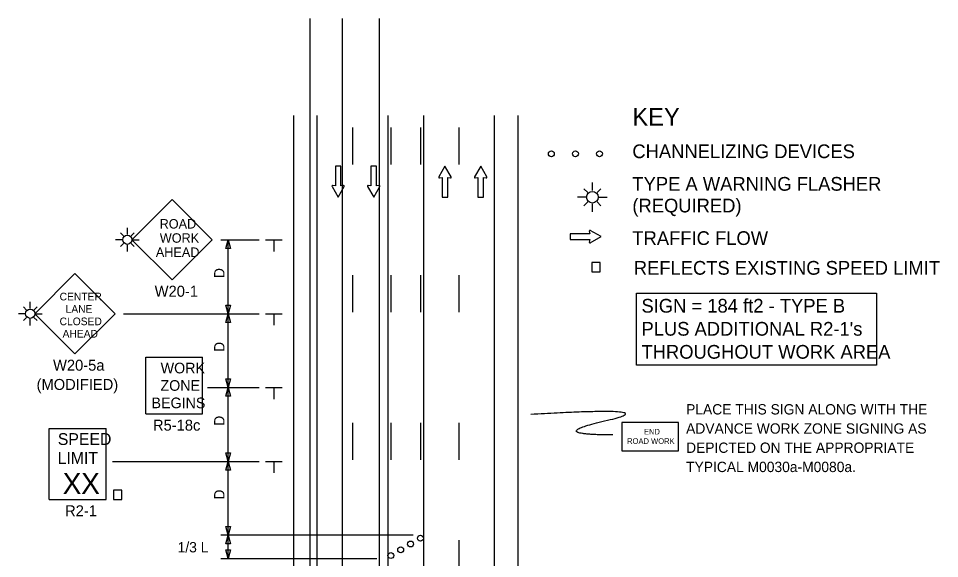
# Model space of a CAD drawing. Extents: x 16765 to 18475, y 6981 to 8262.
# Drawn here: x 16791 to 17415, y 7896 to 8262 of the extents above; entities that cross this region are included whole.
import ezdxf

# ---------------------------------------------------------------- set-up
doc = ezdxf.new("R2010")
doc.units = 0
for name, color, linetype in [('ALI_LEGAL_EX', 7, 'Continuous'), ('MT_SCRATCH_LEVEL_E', 7, 'Continuous'), ('PAVT_EDGE_EX', 7, 'Continuous'), ('TRAFFIC_SIGNS_PR', 7, 'Continuous'), ('TYPICAL_TEXT_DIMEN_EX', 7, 'Continuous'), ('TYPICAL_TEXT_DIMEN_PR', 7, 'Continuous')]:
    doc.layers.add(name, color=color, linetype=linetype)

msp = doc.modelspace()

# ---------------------------------------------------------------- linework, layer by layer
at = {"layer": 'ALI_LEGAL_EX'}
for points in [[(17017.08, 8188.47), (17017.08, 8163.47)], [(17043.08, 8188.47), (17043.08, 8163.47)], [(17063.08, 8188.47), (17063.08, 8163.47)], [(17089.08, 8188.47), (17089.08, 8163.47)], [(17017.08, 8088.47), (17017.08, 8063.47)], [(17043.08, 8088.47), (17043.08, 8063.47)], [(17063.08, 8088.47), (17063.08, 8063.47)], [(17089.08, 8088.47), (17089.08, 8063.47)], [(17017.08, 7988.47), (17017.08, 7963.47)], [(17043.08, 7988.47), (17043.08, 7963.47)], [(17063.08, 7988.47), (17063.08, 7963.47)], [(17089.08, 7988.47), (17089.08, 7963.47)]]:
    msp.add_lwpolyline(points, dxfattribs=at)
at = {"layer": 'MT_SCRATCH_LEVEL_E'}
for p, q in [((17009.24, 8162.18), (17005.5, 8162.18)), ((17005.5, 8162.18), (17005.5, 8148.92)), ((17009.24, 8162.18), (17005.5, 8162.18)), ((17005.5, 8162.18), (17005.5, 8148.92)), ((17009.24, 8148.92), (17009.24, 8162.18)), ((17009.24, 8148.92), (17009.24, 8162.18)), ((17033.31, 8162.18), (17029.57, 8162.18)), ((17029.57, 8162.18), (17029.57, 8148.92)), ((17033.31, 8162.18), (17029.57, 8162.18)), ((17029.57, 8162.18), (17029.57, 8148.92)), ((17033.31, 8148.92), (17033.31, 8162.18)), ((17033.31, 8148.92), (17033.31, 8162.18)), ((17079.72, 8162.18), (17075.61, 8154.94)), ((17079.72, 8162.18), (17075.61, 8154.94)), ((17083.86, 8154.94), (17079.72, 8162.18)), ((17083.86, 8154.94), (17079.72, 8162.18)), ((17103.89, 8162.18), (17099.78, 8154.94)), ((17103.89, 8162.18), (17099.78, 8154.94)), ((17108.03, 8154.94), (17103.89, 8162.18)), ((17108.03, 8154.94), (17103.89, 8162.18)), ((17076.09, 8154.26), (17077.87, 8154.57)), ((17076.09, 8154.26), (17077.87, 8154.57)), ((17077.87, 8154.57), (17077.87, 8141.31)), ((17077.87, 8154.57), (17077.87, 8141.31)), ((17081.61, 8141.31), (17081.61, 8154.57)), ((17081.61, 8154.57), (17083.39, 8154.26)), ((17081.61, 8141.31), (17081.61, 8154.57)), ((17081.61, 8154.57), (17083.39, 8154.26)), ((17100.26, 8154.26), (17102.04, 8154.57)), ((17100.26, 8154.26), (17102.04, 8154.57)), ((17102.04, 8154.57), (17102.04, 8141.31)), ((17102.04, 8154.57), (17102.04, 8141.31)), ((17105.78, 8141.31), (17105.78, 8154.57)), ((17105.78, 8154.57), (17107.56, 8154.26)), ((17105.78, 8141.31), (17105.78, 8154.57)), ((17105.78, 8154.57), (17107.56, 8154.26)), ((17003.24, 8148.55), (17007.39, 8141.31)), ((17003.24, 8148.55), (17007.39, 8141.31)), ((17005.5, 8148.92), (17003.72, 8149.24)), ((17005.5, 8148.92), (17003.72, 8149.24)), ((17007.39, 8141.31), (17011.5, 8148.55)), ((17007.39, 8141.31), (17011.5, 8148.55)), ((17011.02, 8149.24), (17009.24, 8148.92)), ((17011.02, 8149.24), (17009.24, 8148.92)), ((17027.31, 8148.55), (17031.46, 8141.31)), ((17027.31, 8148.55), (17031.46, 8141.31)), ((17029.57, 8148.92), (17027.79, 8149.24)), ((17029.57, 8148.92), (17027.79, 8149.24)), ((17031.46, 8141.31), (17035.57, 8148.55)), ((17031.46, 8141.31), (17035.57, 8148.55)), ((17035.09, 8149.24), (17033.31, 8148.92)), ((17035.09, 8149.24), (17033.31, 8148.92)), ((17077.87, 8141.31), (17081.61, 8141.31)), ((17077.87, 8141.31), (17081.61, 8141.31)), ((17102.04, 8141.31), (17105.78, 8141.31)), ((17102.04, 8141.31), (17105.78, 8141.31)), ((17177.76, 8116.38), (17164.5, 8116.38)), ((17164.5, 8116.38), (17164.5, 8112.64)), ((17177.76, 8116.38), (17164.5, 8116.38)), ((17164.5, 8116.38), (17164.5, 8112.64)), ((17177.45, 8118.16), (17177.76, 8116.38)), ((17177.45, 8118.16), (17177.76, 8116.38)), ((17185.37, 8114.53), (17178.13, 8118.64)), ((17185.37, 8114.53), (17178.13, 8118.64)), ((17178.13, 8110.38), (17185.37, 8114.53)), ((17178.13, 8110.38), (17185.37, 8114.53)), ((17164.5, 8112.64), (17177.76, 8112.64)), ((17164.5, 8112.64), (17177.76, 8112.64)), ((17177.76, 8112.64), (17177.45, 8110.86)), ((17177.76, 8112.64), (17177.45, 8110.86))]:
    msp.add_line(p, q, dxfattribs=at)
for centre, start, end in [((17076.01, 8154.71), 150.42484, 279.96381), ((17076.01, 8154.71), 150.42484, 279.96381), ((17083.45, 8154.71), 260.03619, 29.77312), ((17083.45, 8154.71), 260.03619, 29.77312), ((17100.18, 8154.71), 150.42484, 279.96381), ((17100.18, 8154.71), 150.42484, 279.96381), ((17107.62, 8154.71), 260.03619, 29.77312), ((17107.62, 8154.71), 260.03619, 29.77312), ((17003.65, 8148.78), 80.03619, 209.77312), ((17003.65, 8148.78), 80.03619, 209.77312), ((17011.09, 8148.78), 330.42484, 99.96381), ((17011.09, 8148.78), 330.42484, 99.96381), ((17027.72, 8148.78), 80.03619, 209.77312), ((17027.72, 8148.78), 80.03619, 209.77312), ((17035.16, 8148.78), 330.42484, 99.96381), ((17035.16, 8148.78), 330.42484, 99.96381), ((17177.91, 8118.23), 60.42484, 189.96381), ((17177.91, 8118.23), 60.42484, 189.96381), ((17177.91, 8110.79), 170.03619, 299.77312), ((17177.91, 8110.79), 170.03619, 299.77312)]:
    msp.add_arc(centre, 0.463, start, end, dxfattribs=at)
at = {"layer": 'PAVT_EDGE_EX'}
for p, q in [((16988.15, 8262.34), (16988.15, 7433.15)), ((17010.15, 8262.34), (17010.15, 7433.15)), ((17035.15, 8262.34), (17035.15, 7433.15)), ((16977.08, 8196.54), (16977.08, 7351.89)), ((16993.08, 8196.54), (16993.08, 7351.89)), ((17041.08, 8196.54), (17041.08, 7351.89)), ((17065.08, 8196.54), (17065.08, 7861.14)), ((17113.08, 8196.54), (17113.08, 7351.89)), ((17129.08, 8196.54), (17129.08, 7351.89)), ((17089.08, 7909.01), (17089.08, 7844.93))]:
    msp.add_line(p, q, dxfattribs=at)
at = {"layer": 'TRAFFIC_SIGNS_PR'}
for p, q in [((17179.52, 8145.68), (17179.52, 8151.3)), ((17176.38, 8144.38), (17173.75, 8147.01)), ((17182.66, 8144.38), (17185.29, 8147.01)), ((16895.02, 8139.66), (16867.83, 8112.47)), ((16922.21, 8112.47), (16895.02, 8139.66)), ((17175.58, 8141.24), (17169.55, 8141.24)), ((17183.46, 8141.24), (17189.55, 8141.24)), ((17176.38, 8138.11), (17173.75, 8135.47)), ((17179.52, 8131.3), (17179.52, 8136.81)), ((17182.66, 8138.11), (17185.29, 8135.48)), ((16864.68, 8116.03), (16864.68, 8120.53)), ((16862.17, 8114.99), (16860.06, 8117.1)), ((16867.19, 8114.99), (16869.3, 8117.1)), ((16861.53, 8112.47), (16856.69, 8112.47)), ((16862.17, 8109.96), (16860.06, 8107.85)), ((16864.68, 8104.51), (16864.68, 8108.92)), ((16867.19, 8109.96), (16869.3, 8107.85)), ((16867.83, 8112.47), (16895.02, 8085.29)), ((16867.83, 8112.47), (16872.72, 8112.47)), ((16895.02, 8085.29), (16922.21, 8112.47)), ((16829.24, 8089.49), (16802.09, 8062.34)), ((16856.39, 8062.34), (16829.24, 8089.49)), ((16798.93, 8065.9), (16798.93, 8070.4)), ((16796.42, 8064.85), (16794.31, 8066.96)), ((16801.45, 8064.85), (16803.55, 8066.96)), ((16795.78, 8062.34), (16790.94, 8062.34)), ((16796.42, 8059.83), (16794.31, 8057.72)), ((16798.93, 8054.37), (16798.93, 8058.79)), ((16801.45, 8059.83), (16803.55, 8057.72)), ((16802.09, 8062.34), (16806.97, 8062.34)), ((16802.09, 8062.34), (16829.24, 8035.19)), ((16829.24, 8035.19), (16856.39, 8062.34)), ((16877.23, 7994.57), (16877.23, 8032.97)), ((16877.23, 8032.97), (16915.63, 8032.97)), ((16915.63, 7994.57), (16915.63, 8032.97)), ((16877.23, 7994.57), (16915.63, 7994.57)), ((16811.85, 7984.58), (16850.25, 7984.58)), ((16811.85, 7936.58), (16811.85, 7984.58)), ((16850.25, 7936.58), (16850.25, 7984.58)), ((16811.85, 7936.58), (16850.25, 7936.58))]:
    msp.add_line(p, q, dxfattribs=at)
for points in [[(17179.22, 8090.78), (17184.81, 8090.78), (17184.81, 8096.95), (17179.22, 8096.95)], [(17199.42, 7969.4), (17237.82, 7969.4), (17237.82, 7988.6), (17199.42, 7988.6)], [(16855.27, 7936.58), (16860.86, 7936.58), (16860.86, 7942.75), (16855.27, 7942.75)]]:
    msp.add_lwpolyline(points, close=True, dxfattribs=at)
for centre, radius in [((17151.75, 8170.64), 2), ((17168.05, 8170.64), 2), ((17184.35, 8170.64), 2), ((17179.52, 8141.24), 3.94), ((16864.68, 8112.47), 3.15), ((16798.93, 8062.34), 3.15), ((17056.41, 7906.35), 2), ((17063.08, 7910.27), 2), ((17049.75, 7902.43), 2), ((17043.08, 7898.51), 2)]:
    msp.add_circle(centre, radius, dxfattribs=at)
msp.add_open_spline([(17193.47, 7980.25), (17146.24, 7980.25), (17231.26, 7999.59), (17137.93, 7994.1)], degree=2, dxfattribs=at)
at = {"layer": 'TYPICAL_TEXT_DIMEN_EX'}
msp.add_lwpolyline([(17209.41, 8076.18), (17371.84, 8076.18), (17371.84, 8027.4), (17209.41, 8027.4)], close=True, dxfattribs=at)
at = {"layer": 'TYPICAL_TEXT_DIMEN_PR'}
for p, q in [((16927.98, 8112.27), (16953.98, 8112.27)), ((16931.41, 8106.4), (16932.98, 8112.27)), ((16932.98, 8112.27), (16934.55, 8106.4)), ((16932.98, 8062.27), (16932.98, 8112.27)), ((16958.23, 8112.27), (16969.48, 8112.27)), ((16963.86, 8112.27), (16963.86, 8104.48)), ((16932.98, 8106.4), (16931.41, 8106.4)), ((16934.55, 8106.4), (16932.98, 8106.4)), ((16932.98, 8062.27), (16931.41, 8068.13)), ((16931.41, 8068.13), (16932.98, 8068.13)), ((16932.98, 8068.13), (16934.55, 8068.13)), ((16934.55, 8068.13), (16932.98, 8062.27)), ((16862.03, 8062.27), (16953.98, 8062.27)), ((16931.41, 8056.4), (16932.98, 8062.27)), ((16932.98, 8062.27), (16934.55, 8056.4)), ((16932.98, 8012.27), (16932.98, 8062.27)), ((16958.23, 8062.27), (16969.48, 8062.27)), ((16963.86, 8062.27), (16963.86, 8054.48)), ((16932.98, 8056.4), (16931.41, 8056.4)), ((16934.55, 8056.4), (16932.98, 8056.4)), ((16932.98, 8012.27), (16931.41, 8018.13)), ((16931.41, 8018.13), (16932.98, 8018.13)), ((16932.98, 8018.13), (16934.55, 8018.13)), ((16934.55, 8018.13), (16932.98, 8012.27)), ((16918.89, 8012.27), (16953.98, 8012.27)), ((16931.41, 8006.4), (16932.98, 8012.27)), ((16932.98, 8012.27), (16934.55, 8006.4)), ((16932.98, 7962.27), (16932.98, 8012.27)), ((16958.23, 8012.27), (16969.48, 8012.27)), ((16963.86, 8012.27), (16963.86, 8004.48)), ((16932.98, 8006.4), (16931.41, 8006.4)), ((16934.55, 8006.4), (16932.98, 8006.4)), ((16932.98, 7962.27), (16931.41, 7968.13)), ((16931.41, 7968.13), (16932.98, 7968.13)), ((16932.98, 7968.13), (16934.55, 7968.13)), ((16934.55, 7968.13), (16932.98, 7962.27)), ((16854.63, 7962.27), (16953.98, 7962.27)), ((16931.41, 7956.4), (16932.98, 7962.27)), ((16932.98, 7962.27), (16934.55, 7956.4)), ((16932.98, 7912.27), (16932.98, 7962.27)), ((16958.23, 7962.27), (16969.48, 7962.27)), ((16963.86, 7962.27), (16963.86, 7954.48)), ((16932.98, 7956.4), (16931.41, 7956.4)), ((16934.55, 7956.4), (16932.98, 7956.4)), ((16932.98, 7912.27), (16931.41, 7918.13)), ((16931.41, 7918.13), (16932.98, 7918.13)), ((16932.98, 7918.13), (16934.55, 7918.13)), ((16934.55, 7918.13), (16932.98, 7912.27)), ((17058.17, 7912.27), (16927.98, 7912.27)), ((16931.41, 7906.4), (16932.98, 7912.27)), ((16932.98, 7896.5), (16932.98, 7912.27)), ((16932.98, 7912.27), (16934.55, 7906.4)), ((16932.98, 7906.4), (16931.41, 7906.4)), ((16932.98, 7896.5), (16931.41, 7902.36)), ((16931.41, 7902.36), (16932.98, 7902.36)), ((16934.55, 7906.4), (16932.98, 7906.4)), ((16932.98, 7902.36), (16934.55, 7902.36)), ((16934.55, 7902.36), (16932.98, 7896.5)), ((16927.98, 7896.51), (17033.61, 7896.51))]:
    msp.add_line(p, q, dxfattribs=at)

# ---------------------------------------------------------------- texts
at = {"layer": 'TRAFFIC_SIGNS_PR'}
for s, height, p in [('ROAD', 6.408, (16886.55, 8120.02)), ('WORK', 6.408, (16886.66, 8110.41)), ('AHEAD', 6.408, (16883.97, 8100.8)), ('CENTER', 5.2, (16818.82, 8071.34)), ('W20-1', 7.449, (16883.17, 8073.84)), ('LANE', 5.2, (16822.89, 8062.94)), ('CLOSED', 5.2, (16818.82, 8054.54)), ('AHEAD', 5.2, (16820.84, 8046.14)), ('W20-5a', 7.44, (16814.38, 8023.75)), ('WORK', 7.217, (16887.23, 8021.93)), ('(MODIFIED)', 7.44, (16803.23, 8010.71)), ('ZONE', 7.217, (16887.11, 8010.12)), ('BEGINS', 7.217, (16881.04, 7998.32)), ('PLACE THIS SIGN ALONG WITH THE', 7, (17242.97, 7994.08)), ('R5-18c', 7.44, (16882.04, 7983.13)), ('END', 3.831, (17214.42, 7980.53)), ('ADVANCE WORK ZONE SIGNING AS', 7, (17242.97, 7981.08)), ('SPEED', 8, (16817.62, 7973.44)), ('ROAD WORK', 3.831, (17203.03, 7974.15)), ('DEPICTED ON THE APPROPRIATE', 7, (17242.97, 7968.08)), ('LIMIT', 8, (16817.46, 7960.64)), ('TYPICAL M0030a-M0080a.', 7, (17242.97, 7955.08)), ('XX', 14.031, (16820.97, 7940.34)), ('R2-1', 7.44, (16822.53, 7925.14))]:
    msp.add_text(s, height=height, dxfattribs=at).set_placement(p)
at = {"layer": 'TYPICAL_TEXT_DIMEN_EX'}
for s, height, p in [('KEY', 12, (17206.59, 8189.74)), ('CHANNELIZING DEVICES', 9.3, (17206.59, 8167.69)), ('TYPE A WARNING FLASHER', 9.3, (17206.59, 8145.64)), ('(REQUIRED)', 9.3, (17206.59, 8130.94)), ('TRAFFIC FLOW', 9.3, (17206.59, 8108.89)), ('REFLECTS EXISTING SPEED LIMIT', 9.3, (17207.55, 8088.75)), ('SIGN = 184 ft2 - TYPE B', 9.3, (17212.75, 8063.06)), ("PLUS ADDITIONAL R2-1's", 9.3, (17212.75, 8047.46)), ('THROUGHOUT WORK AREA', 9.3, (17212.75, 8031.86))]:
    msp.add_text(s, height=height, dxfattribs=at).set_placement(p)
at = {"layer": 'TYPICAL_TEXT_DIMEN_PR'}
for p in [(16930.42, 8086.48), (16930.42, 8036.48), (16930.42, 7986.48), (16930.42, 7936.48)]:
    msp.add_text('D', height=7, rotation=90, dxfattribs=at).set_placement(p)
msp.add_text('1/3 L', height=7, dxfattribs=at).set_placement((16898.74, 7900.69))

doc.saveas('drawing.dxf')
